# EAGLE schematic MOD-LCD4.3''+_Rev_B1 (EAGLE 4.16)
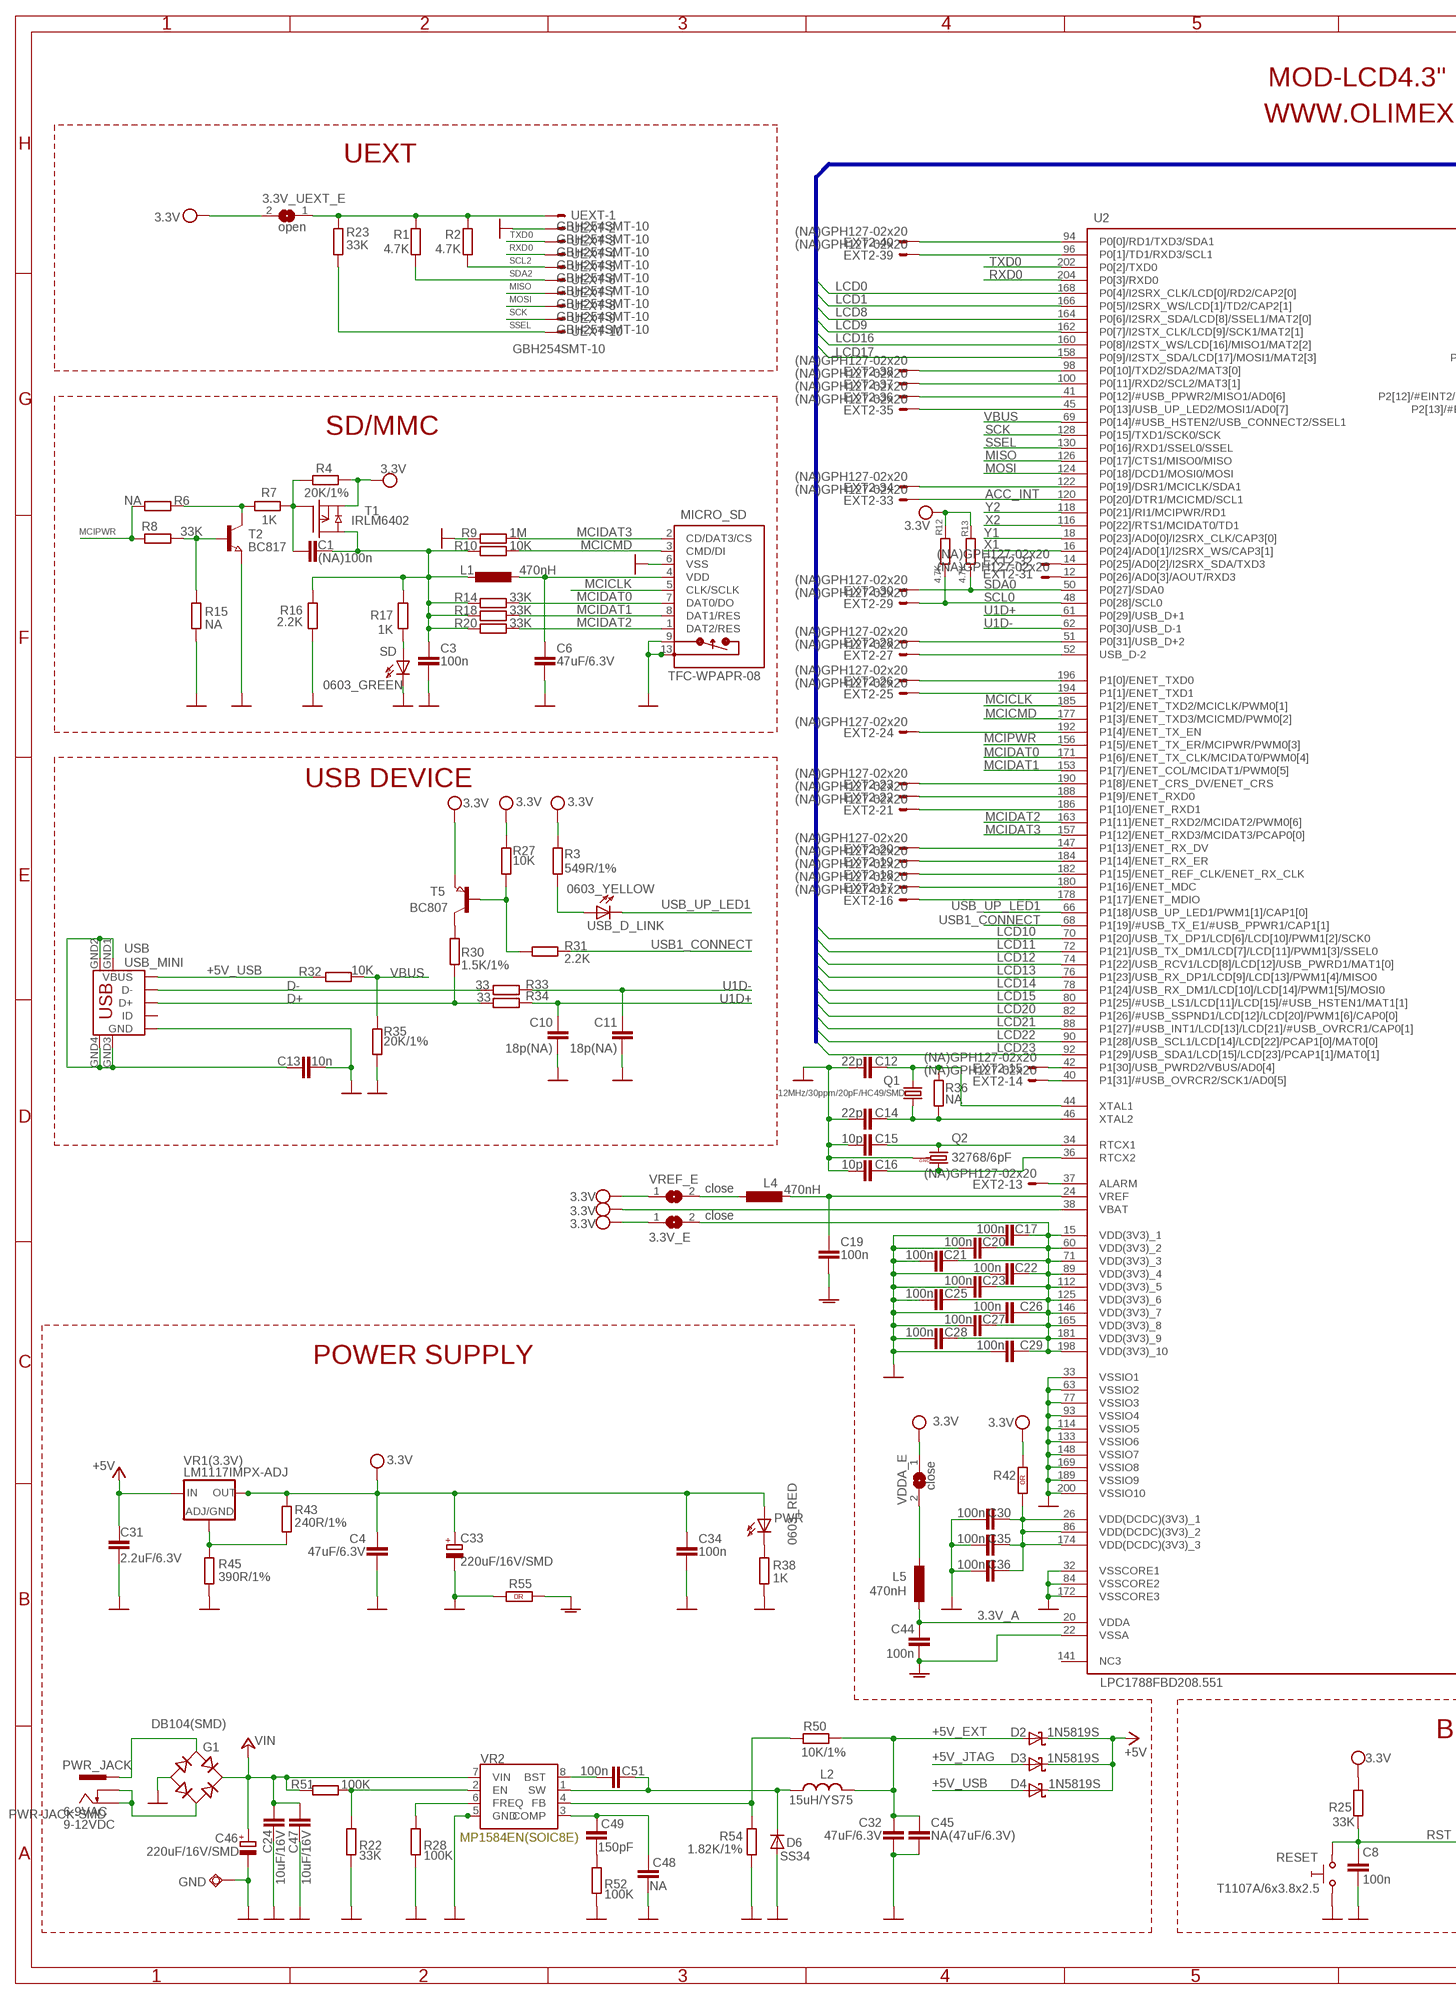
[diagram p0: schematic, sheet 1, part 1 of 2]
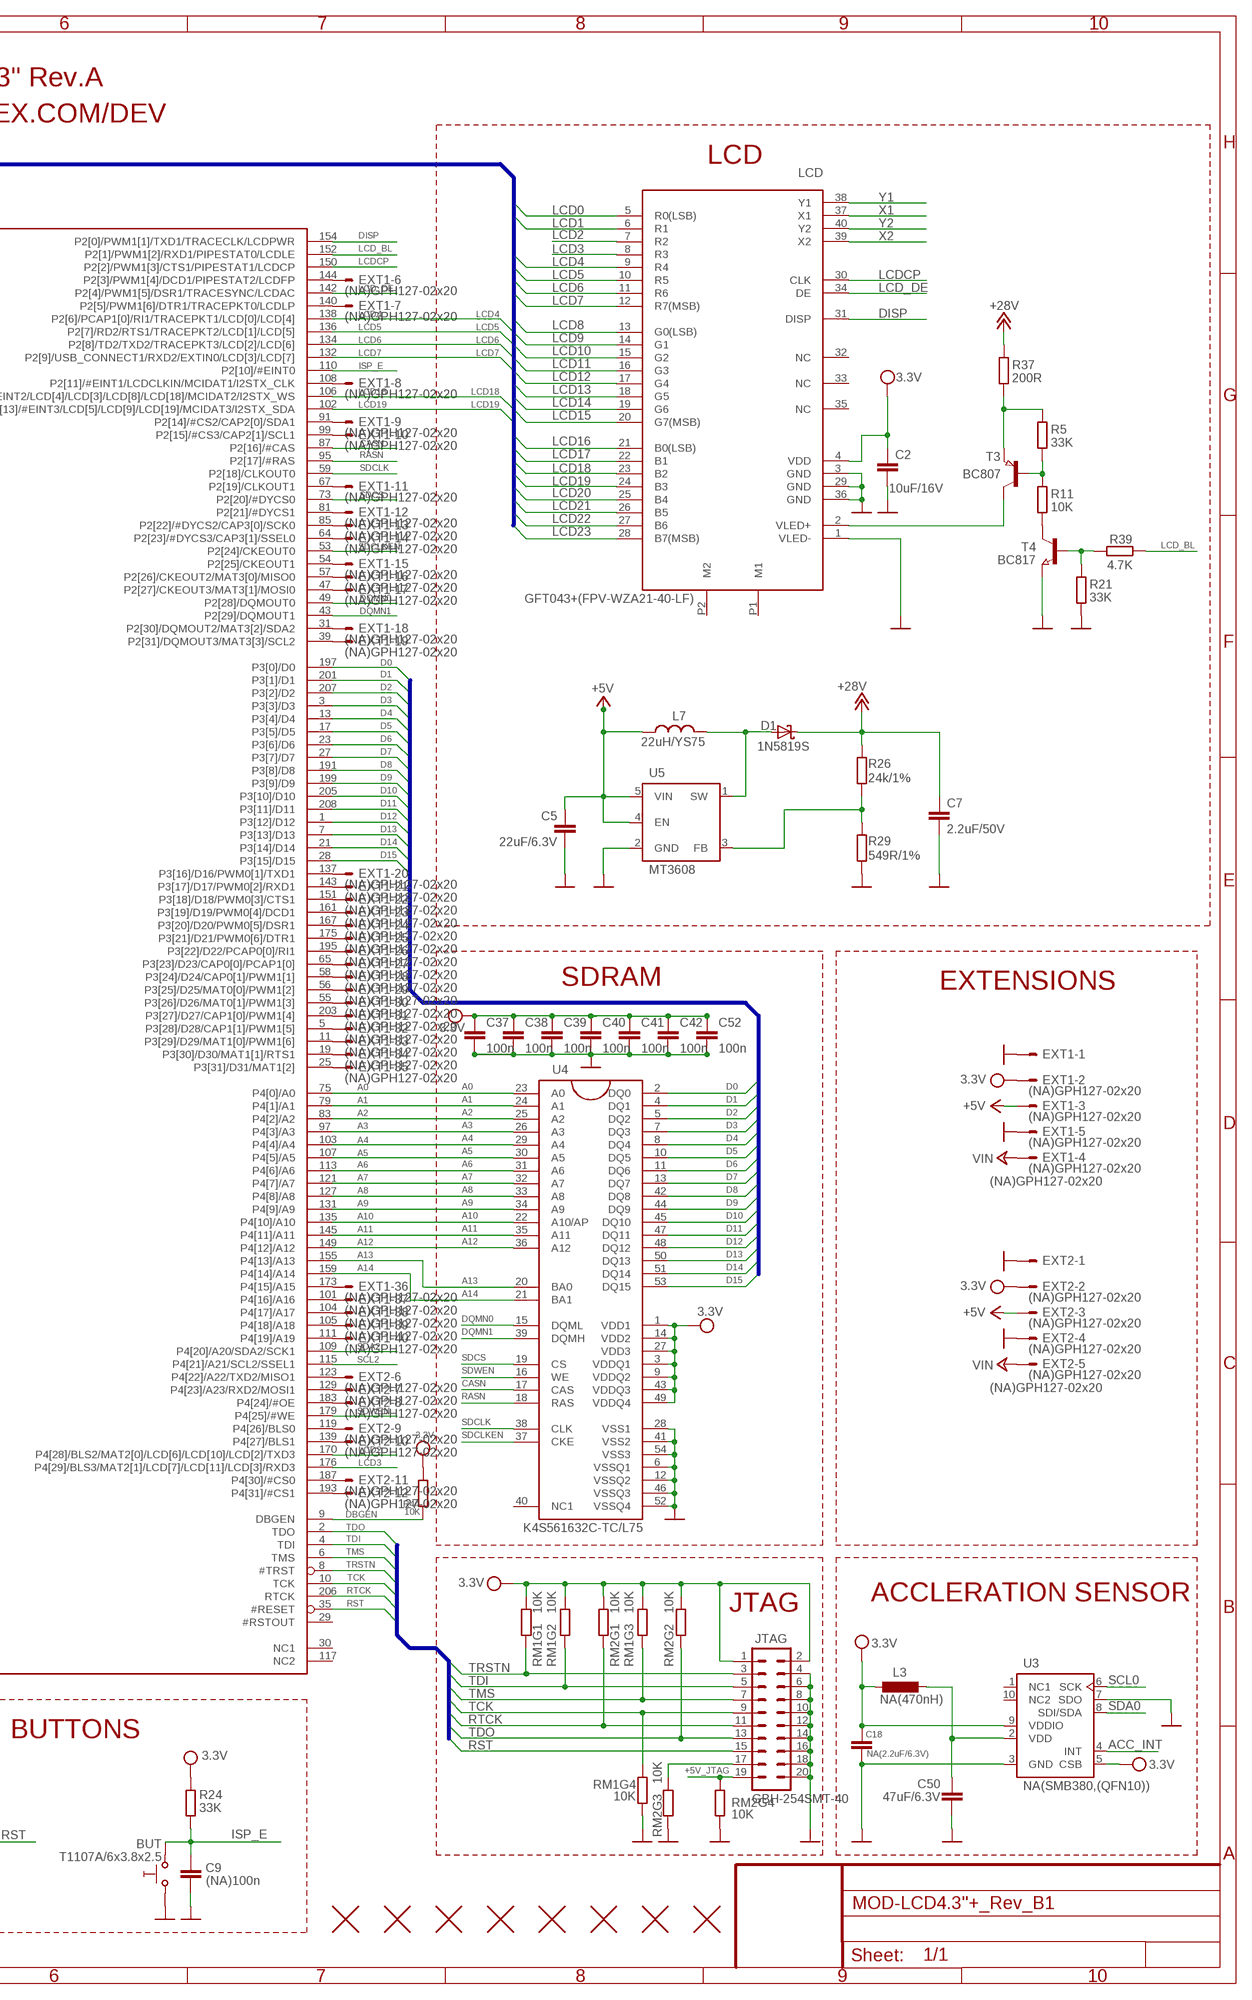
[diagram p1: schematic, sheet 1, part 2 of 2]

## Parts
3.3V_E  close  SJSJ_1_SMALLER_CLOSE  [SJ_1_SMALLER_CLOSE]
3.3V_UEXT_E  open  SJSJ_SMALLER  [SJ_1_SMALLER]
BUT  T1107A/6x3.8x2.5  SW-TAKT6  [SW-TAKT_6X3.5_SMD]
C1  (NA)100n  C0603  [C0603]
C2  10uF/16V  C-EUC0805_5MIL_DWS  [C0805_5MIL_DWS]
C3  100n  C0603  [C0603]
C4  47uF/6.3V  C0805  [C0805]
C5  22uF/6.3V  C-EUC0603_DWS  [C0603_DWS]
C6  47uF/6.3V  C0805  [C0805]
C7  2.2uF/50V  C-EUC0603_DWS  [C0603_DWS]
C8  100n  C0603  [C0603]
C9  (NA)100n  C0603  [C0603]
C10  18p(NA)  C0603  [C0603]
C11  18p(NA)  C0603  [C0603]
C12  22p  C0603  [C0603]
C13  10n  C0603  [C0603]
C14  22p  C0603  [C0603]
C15  10p  C0603  [C0603]
C16  10p  C0603  [C0603]
C17  100n  C0603  [C0603]
C18  NA(2.2uF/6.3V)  C0603  [C0603]
C19  100n  C0603  [C0603]
C20  100n  C0603  [C0603]
C21  100n  C0603  [C0603]
C22  100n  C0603  [C0603]
C23  100n  C0603  [C0603]
C24  10uF/16V  C-EUC0805_5MIL_DWS  [C0805_5MIL_DWS]
C25  100n  C0603  [C0603]
C26  100n  C0603  [C0603]
C27  100n  C0603  [C0603]
C28  100n  C0603  [C0603]
C29  100n  C0603  [C0603]
C30  100n  C0603  [C0603]
C31  2.2uF/6.3V  C-EUC0603_DWS  [C0603_DWS]
C32  47uF/6.3V  C0805  [C0805]
C33  220uF/16V/SMD  CPOL-EU153CLV-0605  [153CLV-0605]
C34  100n  C0603  [C0603]
C35  100n  C0603  [C0603]
C36  100n  C0603  [C0603]
C37  100n  C0603  [C0603]
C38  100n  C0603  [C0603]
C39  100n  C0603  [C0603]
C40  100n  C0603  [C0603]
C41  100n  C0603  [C0603]
C42  100n  C0603  [C0603]
C44  100n  C0603  [C0603]
C45  NA(47uF/6.3V)  C0805  [C0805]
C46  220uF/16V/SMD  CPOL-EU153CLV-0605  [153CLV-0605]
C47  10uF/16V  C-EUC0805_5MIL_DWS  [C0805_5MIL_DWS]
C48  NA  C0603  [C0603]
C49  150pF  C0603  [C0603]
C50  47uF/6.3V  C0805  [C0805]
C51  100n  C0603  [C0603]
C52  100n  C0603  [C0603]
D1  1N5819S  SCHOTKKY7.62SS2  [MLL-41]
D2  1N5819S  SCHOTKKY7.62SS2  [MLL-41]
D3  1N5819S  SCHOTKKY7.62SS2  [MLL-41]
D4  1N5819S  SCHOTKKY7.62SS2  [MLL-41]
D6  SS34  D-MLL-41  [MELF-MLL41]
EXT1  (NA)GPH127-02x20  ML40M50E  [ML40_50MILS_M]
EXT2  (NA)GPH127-02x20  ML40M50E  [ML40_50MILS_M]
G1  DB104(SMD)  B-DIL3  [DB104_SMD]
GND  TESTPAD3  [TEST_PAD40/70/SQUARE]
JTAG  GBH-254SMT-40  ML20MD  [ML20_S]
L1  470nH  L-EUL0805  [L0805]
L2  15uH/YS75  LLQH88PN100M38  [8X8MM_3131]
L3  NA(470nH)  L-EUL0805  [L0805]
L4  470nH  L-EUL0805  [L0805]
L5  470nH  L-EUL0805  [L0805]
L7  22uH/YS75  LLQH88PN100M38  [8X8MM_3131]
LCD  GFT043+(FPV-WZA21-40-LF)  [GFT043(40PINS)]
MICRO_SD  TFC-WPAPR-08  MICRO_SD/MMC_CP_NEWTFC-WPAPR-08  [TFC-WPAPR-08]
PWR  0603_RED  LED0603DWS  [LED-0603]
PWR_JACK  PWR-JACK-SMD  PWR-JAKDCJ-W  [PWR-JACK-SMD]
Q1  12MHz/30ppm/20pF/HC49/SMD  HC49/SHC49/SMD_THIN&SHORT  [HC49/SMD2_THIN&SHORT]
Q2  32768/6pF  Q_GND1  [TC26H_3_REPAIR_SMD]
R1  4.7K  R-EU_R0603  [R0603]
R2  4.7K  R-EU_R0603  [R0603]
R3  549R/1%  R-EU_R0603  [R0603]
R4  20K/1%  R0603  [R0603]
R5  33K  R0603  [R0603]
R6  NA  R0603  [R0603]
R7  1K  R0603  [R0603]
R8  33K  R0603  [R0603]
R9  1M  R0603  [R0603]
R10  10K  R0603  [R0603]
R11  10K  R0603  [R0603]
R12  4.7K  R-EU_R0603  [R0603]
R13  4.7K  R-EU_R0603  [R0603]
R14  33K  R0603  [R0603]
R15  NA  R0603  [R0603]
R16  2.2K  R0603  [R0603]
R17  1K  R0603  [R0603]
R18  33K  R0603  [R0603]
R20  33K  R0603  [R0603]
R21  33K  R0603  [R0603]
R22  33K  R-EU_R0603  [R0603]
R23  33K  R0603  [R0603]
R24  33K  R0603  [R0603]
R25  33K  R0603  [R0603]
R26  24k/1%  R-EU_R0603  [R0603]
R27  10K  R0603  [R0603]
R28  100K  R-EU_R0603  [R0603]
R29  549R/1%  R-EU_R0603  [R0603]
R30  1.5K/1%  R0603  [R0603]
R31  2.2K  R0603  [R0603]
R32  10K  R0603  [R0603]
R33  33  R0603  [R0603]
R34  33  R0603  [R0603]
R35  20K/1%  R0603  [R0603]
R36  NA  R-EU_R0603  [R0603]
R37  200R  R0805  [R0805]
R38  1K  R0603  [R0603]
R39  4.7K  R-EU_R0603  [R0603]
R42  R_0R0R(NA)  [0603_0R]
R43  240R/1%  R-EU_R0603  [R0603]
R44  10K  R0603  [R0603]
R45  390R/1%  R-EU_R0603  [R0603]
R50  10K/1%  R-EU_R0603  [R0603]
R51  100K  R-EU_R0603  [R0603]
R52  100K  R-EU_R0603  [R0603]
R54  1.82K/1%  R-EU_R0603  [R0603]
R55  R_0R0R(NA)  [0603_0R]
RESET  T1107A/6x3.8x2.5  SW-TAKT6  [SW-TAKT_6X3.5_SMD]
RM1  10K  R_MATRIX_4E  [R_MATRIX_4]
RM2  10K  R_MATRIX_4E  [R_MATRIX_4]
SD  0603_GREEN  LED0603DWS  [LED-0603]
T1  IRLM6402  IRLML6402  [SOT23]
T2  BC817  NPN-TRANSISTOR_SOT23  [SOT23]
T3  BC807  PNP-TRANSISTOR_SOT23  [SOT23]
T4  BC817  NPN-TRANSISTOR_SOT23  [SOT23]
T5  BC807  PNP-TRANSISTOR_SOT23  [SOT23]
U2  LPC1788FBD208.551  LPC2478""  [LQFP208]
U3  NA(SMB380,(QFN10))  SMB3801  [QFN10]
U4  K4S561632C-TC/L75  [54TSOPII]
U5  MT3608  [SOT23-6]
U$1  FIDUCIAL1X2  [FIDUCIAL-1X2]
U$2  FIDUCIAL1X2  [FIDUCIAL-1X2]
U$3  FIDUCIAL1X2  [FIDUCIAL-1X2]
U$6  FIDUCIAL1X2  [FIDUCIAL-1X2]
U$9  FIDUCIAL1X2  [FIDUCIAL-1X2]
U$10  FIDUCIAL1X2  [FIDUCIAL-1X2]
U$12  FIDUCIAL1X2  [FIDUCIAL-1X2]
U$13  FIDUCIAL1X2  [FIDUCIAL-1X2]
UEXT  GBH254SMT-10  ML10MDE  [ML10_S]
USB  USB_MINI  MINI_USB9  [USB_MINI_9PIN]
USB_D_LINK  0603_YELLOW  LED0603DWS  [LED-0603]
VDDA_E  close  SJSJ_1_SMALLER_CLOSE  [SJ_1_SMALLER_CLOSE]
VR1(3.3V)  LM1117IMPX-ADJ  LM1117  [SOT223]
VR2  MP1584EN(SOIC8E)  [SOIC8E]
VREF_E  close  SJSJ_1_SMALLER_CLOSE  [SJ_1_SMALLER_CLOSE]

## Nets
3.3V_A: C44.2 L5.1 U2.20(VDDA)
3.3V_MCU: 3.3V_E.2 C17.2 C20.2 C21.2 C22.2 C23.2 C25.2 C26.2 C27.2 C28.2 C29.2 U2.15(VDD(3V3)_1) U2.60(VDD(3V3)_2) U2.71(VDD(3V3)_3) U2.89(VDD(3V3)_4) U2.112(VDD(3V3)_5) U2.125(VDD(3V3)_6) U2.146(VDD(3V3)_7) U2.165(VDD(3V3)_8) U2.181(VDD(3V3)_9) U2.198(VDD(3V3)_10)
+5V: C5.1 C31.1 D2.K(C) D3.K(C) D4.K(C) EXT1.3 EXT2.3 L7.1 U5.4(EN) U5.5(VIN) VR1(3.3V).3(IN)
+5V_EXT: C32.2 C45.2 D2.A L2.2 R50.2
+5V_JTAG: D3.A JTAG.19 RM2.4.2
+5V_USB: D4.A R32.1 USB.VBUS
+12V: C7.1 D1.K(C) R26.2 R37.1 ; supply symbol labelled +28V
+24V: C24.1 C46.+ C47.1 EXT1.4 EXT2.5 G1.+ R51.2 VR2.7(VIN) ; supply symbol labelled VIN
A0: U2.75(P4[0]/A0) U4.23(A0)
A1: U2.79(P4[1]/A1) U4.24(A1)
A2: U2.83(P4[2]/A2) U4.25(A2)
A3: U2.97(P4[3]/A3) U4.26(A3)
A4: U2.103(P4[4]/A4) U4.29(A4)
A5: U2.107(P4[5]/A5) U4.30(A5)
A6: U2.113(P4[6]/A6) U4.31(A6)
A7: U2.121(P4[7]/A7) U4.32(A7)
A8: U2.127(P4[8]/A8) U4.33(A8)
A9: U2.131(P4[9]/A9) U4.34(A9)
A10: U2.135(P4[10]/A10) U4.22(A10/AP)
A11: U2.145(P4[11]/A11) U4.35(A11)
A12: U2.149(P4[12]/A12) U4.36(A12)
A13: U2.155(P4[13]/A13) U4.20(BA0)
A14: U2.159(P4[14]/A14) U4.21(BA1)
ACC_INT: EXT2.33 U2.120(P0[20]/DTR1/MCICMD/SCL1) U3.4(INT)
CASN: U2.87(P2[16]/#CAS) U4.17(CAS)
D0: U2.197(P3[0]/D0) U4.2(DQ0)
D1: U2.201(P3[1]/D1) U4.4(DQ1)
D2: U2.207(P3[2]/D2) U4.5(DQ2)
D3: U2.3(P3[3]/D3) U4.7(DQ3)
D4: U2.13(P3[4]/D4) U4.8(DQ4)
D5: U2.17(P3[5]/D5) U4.10(DQ5)
D6: U2.23(P3[6]/D6) U4.11(DQ6)
D7: U2.27(P3[7]/D7) U4.13(DQ7)
D8: U2.191(P3[8]/D8) U4.42(DQ8)
D9: U2.199(P3[9]/D9) U4.44(DQ9)
D10: U2.205(P3[10]/D10) U4.45(DQ10)
D11: U2.208(P3[11]/D11) U4.47(DQ11)
D12: U2.1(P3[12]/D12) U4.48(DQ12)
D13: U2.7(P3[13]/D13) U4.50(DQ13)
D14: U2.21(P3[14]/D14) U4.51(DQ14)
D15: U2.28(P3[15]/D15) U4.53(DQ15)
D+: R30.1 R34.1 USB.D+
D-: R33.1 USB.D-
DBGEN: R44.1 U2.9(DBGEN)
DISP: LCD.31(DISP) U2.154(P2[0]/PWM1[1]/TXD1/TRACECLK/LCDPWR)
DQMN0: U2.49(P2[28]/DQMOUT0) U4.15(DQML)
DQMN1: U2.43(P2[29]/DQMOUT1) U4.39(DQMH)
GND: BUT.P$2 C2.2 C3.1 C4.1 C5.2 C6.1 C7.2 C8.1 C9.1 C10.2 C11.2 C12.1 C13.1 C14.1 C15.1 C16.1 C17.1 C18.1 C20.1 C21.1 C22.1 C23.1 C24.2 C25.1 C26.1 C27.1 C28.1 C29.1 C30.1 C31.2 C32.1 C33.- C34.1 C35.1 C36.1 C37.1 C38.1 C39.1 C40.1 C41.1 C42.1 C45.1 C46.- C47.2 C48.2 C50.1 C52.1 D6.2(A) EXT1.1 EXT1.5 EXT2.1 EXT2.4 G1.- GND.P$1(PP) JTAG.4 JTAG.6 JTAG.8 JTAG.10 JTAG.12 JTAG.14 JTAG.16 JTAG.18 JTAG.20 LCD.1(VLED-) LCD.3(GND) LCD.29(GND) LCD.36(GND) MICRO_SD.6(VSS) MICRO_SD.9(CP_E) MICRO_SD.10(PACK1) MICRO_SD.11(PACK2) MICRO_SD.12(PACK3) MICRO_SD.13(PACK4) Q2.GND R9.1 R15.1 R16.1 R21.2 R22.1 R28.1 R29.1 R35.2 R38.2 R45.1 R52.1 R54.1 R55.2(1.2) RESET.P$2 RM1.4.1 RM2.3.1 RM2.4.1 SD.C T2.2(E) T4.2(E) U2.32(VSSCORE1) U2.33(VSSIO1) U2.63(VSSIO2) U2.77(VSSIO3) U2.84(VSSCORE2) U2.93(VSSIO4) U2.114(VSSIO5) U2.133(VSSIO6) U2.148(VSSIO7) U2.169(VSSIO8) U2.172(VSSCORE3) U2.189(VSSIO9) U2.200(VSSIO10) U3.3(GND) U3.7(SDO) U4.6(VSSQ1) U4.12(VSSQ2) U4.28(VSS1) U4.41(VSS2) U4.46(VSSQ3) U4.52(VSSQ4) U4.54(VSS3) U5.2(GND) UEXT.2 USB.GND VR2.5(GND) VR2.EP VR2.EP1(EP)
GNDA: C19.1 C44.1 R55.1(1.1) U2.22(VSSA)
ISP_E: BUT.P$1 C9.2 R24.1 U2.110(P2[10]/#EINT0)
LCD0: LCD.5(R0(LSB)) U2.168(P0[4]/I2SRX_CLK/LCD[0]/RD2/CAP2[0])
LCD1: LCD.6(R1) U2.166(P0[5]/I2SRX_WS/LCD[1]/TD2/CAP2[1])
LCD2: LCD.7(R2) U2.170(P4[28]/BLS2/MAT2[0]/LCD[6]/LCD[10]/LCD[2]/TXD3)
LCD3: LCD.8(R3) U2.176(P4[29]/BLS3/MAT2[1]/LCD[7]/LCD[11]/LCD[3]/RXD3)
LCD4: LCD.9(R4) U2.138(P2[6]/PCAP1[0]/RI1/TRACEPKT1/LCD[0]/LCD[4])
LCD5: LCD.10(R5) U2.136(P2[7]/RD2/RTS1/TRACEPKT2/LCD[1]/LCD[5])
LCD6: LCD.11(R6) U2.134(P2[8]/TD2/TXD2/TRACEPKT3/LCD[2]/LCD[6])
LCD7: LCD.12(R7(MSB)) U2.132(P2[9]/USB_CONNECT1/RXD2/EXTIN0/LCD[3]/LCD[7])
LCD8: LCD.13(G0(LSB)) U2.164(P0[6]/I2SRX_SDA/LCD[8]/SSEL1/MAT2[0])
LCD9: LCD.14(G1) U2.162(P0[7]/I2STX_CLK/LCD[9]/SCK1/MAT2[1])
LCD10: LCD.15(G2) U2.70(P1[20]/USB_TX_DP1/LCD[6]/LCD[10]/PWM1[2]/SCK0)
LCD11: LCD.16(G3) U2.72(P1[21]/USB_TX_DM1/LCD[7]/LCD[11]/PWM1[3]/SSEL0)
LCD12: LCD.17(G4) U2.74(P1[22]/USB_RCV1/LCD[8]/LCD[12]/USB_PWRD1/MAT1[0])
LCD13: LCD.18(G5) U2.76(P1[23]/USB_RX_DP1/LCD[9]/LCD[13]/PWM1[4]/MISO0)
LCD14: LCD.19(G6) U2.78(P1[24]/USB_RX_DM1/LCD[10]/LCD[14]/PWM1[5]/MOSI0)
LCD15: LCD.20(G7(MSB)) U2.80(P1[25]/#USB_LS1/LCD[11]/LCD[15]/#USB_HSTEN1/MAT1[1])
LCD16: LCD.21(B0(LSB)) U2.160(P0[8]/I2STX_WS/LCD[16]/MISO1/MAT2[2])
LCD17: LCD.22(B1) U2.158(P0[9]/I2STX_SDA/LCD[17]/MOSI1/MAT2[3])
LCD18: LCD.23(B2) U2.106(P2[12]/#EINT2/LCD[4]/LCD[3]/LCD[8]/LCD[18]/MCIDAT2/I2STX_WS)
LCD19: LCD.24(B3) U2.102(P2[13]/#EINT3/LCD[5]/LCD[9]/LCD[19]/MCIDAT3/I2STX_SDA)
LCD20: LCD.25(B4) U2.82(P1[26]/#USB_SSPND1/LCD[12]/LCD[20]/PWM1[6]/CAP0[0])
LCD21: LCD.26(B5) U2.88(P1[27]/#USB_INT1/LCD[13]/LCD[21]/#USB_OVRCR1/CAP0[1])
LCD22: LCD.27(B6) U2.90(P1[28]/USB_SCL1/LCD[14]/LCD[22]/PCAP1[0]/MAT0[0])
LCD23: LCD.28(B7(MSB)) U2.92(P1[29]/USB_SDA1/LCD[15]/LCD[23]/PCAP1[1]/MAT0[1])
LCD_BL: R39.1 U2.152(P2[1]/PWM1[2]/RXD1/PIPESTAT0/LCDLE)
LCD_DE: LCD.34(DE) U2.142(P2[4]/PWM1[5]/DSR1/TRACESYNC/LCDAC)
LCDCP: LCD.30(CLK) U2.150(P2[2]/PWM1[3]/CTS1/PIPESTAT1/LCDCP)
MCICLK: MICRO_SD.5(CLK/SCLK) U2.185(P1[2]/ENET_TXD2/MCICLK/PWM0[1])
MCICMD: MICRO_SD.3(CMD/DI) R10.2 U2.177(P1[3]/ENET_TXD3/MCICMD/PWM0[2])
MCIDAT0: MICRO_SD.7(DAT0/DO) R14.2 U2.171(P1[6]/ENET_TX_CLK/MCIDAT0/PWM0[4])
MCIDAT1: MICRO_SD.8(DAT1/RES) R18.2 U2.153(P1[7]/ENET_COL/MCIDAT1/PWM0[5])
MCIDAT2: MICRO_SD.1(DAT2/RES) R20.2 U2.163(P1[11]/ENET_RXD2/MCIDAT2/PWM0[6])
MCIDAT3: MICRO_SD.2(CD/DAT3/CS) R9.2 U2.157(P1[12]/ENET_RXD3/MCIDAT3/PCAP0[0])
MCIPWR: R6.2 R8.2 U2.156(P1[5]/ENET_TX_ER/MCIPWR/PWM0[3])
MISO: U2.126(P0[17]/CTS1/MISO0/MISO) UEXT.7
MMC_VDD: C6.2 L1.1 MICRO_SD.4(VDD)
MOSI: U2.124(P0[18]/DCD1/MOSI0/MOSI) UEXT.8
N$1: C50.2 L3.1 U3.2(VDD)
N$2: C12.2 Q1.1 R36.2 U2.44(XTAL1)
N$3: L5.2 VDDA_E.2
N$4: LCD.2(VLED+) T3.3(C)
N$5: R5.2 R11.2 T3.1(B)
N$6: R11.1 T4.3(C)
N$7: C14.2 Q1.2 R36.1 U2.46(XTAL2)
N$8: C15.2 Q2.2 U2.34(RTCX1)
N$9: C16.2 Q2.1 U2.36(RTCX2)
N$10: R21.1 R39.2 T4.1(B)
N$11: 3.3V_UEXT_E.1 R1.2 R2.2 R23.2 UEXT.1
N$12: EXT1.6 U2.144(P2[3]/PWM1[4]/DCD1/PIPESTAT2/LCDFP)
N$13: EXT1.7 U2.140(P2[5]/PWM1[6]/DTR1/TRACEPKT0/LCDLP)
N$14: EXT1.8 U2.108(P2[11]/#EINT1/LCDCLKIN/MCIDAT1/I2STX_CLK)
N$15: EXT1.9 U2.91(P2[14]/#CS2/CAP2[0]/SDA1)
N$16: R8.1 R15.2 T2.1(B)
N$17: EXT1.10 U2.99(P2[15]/#CS3/CAP2[1]/SCL1)
N$18: EXT1.11 U2.67(P2[19]/CLKOUT1)
N$19: EXT1.12 U2.81(P2[21]/#DYCS1)
N$20: EXT1.13 U2.85(P2[22]/#DYCS2/CAP3[0]/SCK0)
N$21: EXT1.14 U2.64(P2[23]/#DYCS3/CAP3[1]/SSEL0)
N$22: EXT1.15 U2.54(P2[25]/CKEOUT1)
N$23: EXT1.16 U2.57(P2[26]/CKEOUT2/MAT3[0]/MISO0)
N$24: EXT1.17 U2.47(P2[27]/CKEOUT3/MAT3[1]/MOSI0)
N$25: EXT1.18 U2.31(P2[30]/DQMOUT2/MAT3[2]/SDA2)
N$26: EXT1.19 U2.39(P2[31]/DQMOUT3/MAT3[3]/SCL2)
N$27: EXT1.20 U2.137(P3[16]/D16/PWM0[1]/TXD1)
N$28: EXT1.21 U2.143(P3[17]/D17/PWM0[2]/RXD1)
N$29 [pwr]: C51.1 D6.1(C) L2.1 VR2.1(SW)
N$30: EXT1.22 U2.151(P3[18]/D18/PWM0[3]/CTS1)
N$31: R26.1 R29.2 U5.3(FB)
N$32: EXT1.23 U2.161(P3[19]/D19/PWM0[4]/DCD1)
N$33: EXT1.24 U2.167(P3[20]/D20/PWM0[5]/DSR1)
N$34: EXT1.25 U2.175(P3[21]/D21/PWM0[6]/DTR1)
N$35 [pwr]: R50.1 R54.2 VR2.4(FB)
N$36: EXT1.26 U2.195(P3[22]/D22/PCAP0[0]/RI1)
N$37: EXT1.27 U2.65(P3[23]/D23/CAP0[0]/PCAP1[0])
N$38: EXT1.28 U2.58(P3[24]/D24/CAP0[1]/PWM1[1])
N$39: EXT1.29 U2.56(P3[25]/D25/MAT0[0]/PWM1[2])
N$40: EXT1.30 U2.55(P3[26]/D26/MAT0[1]/PWM1[3])
N$41: EXT1.31 U2.203(P3[27]/D27/CAP1[0]/PWM1[4])
N$42: JTAG.17 RM2.3.2
N$43: R6.1 R7.2 T2.3(C)
N$44: EXT1.32 U2.5(P3[28]/D28/CAP1[1]/PWM1[5])
N$45: EXT1.33 U2.11(P3[29]/D29/MAT1[0]/PWM1[6])
N$46: EXT1.34 U2.19(P3[30]/D30/MAT1[1]/RTS1)
N$47: EXT1.35 U2.25(P3[31]/D31/MAT1[2])
N$48: EXT1.36 U2.173(P4[15]/A15)
N$49: EXT1.37 U2.101(P4[16]/A16)
N$50: EXT1.38 U2.104(P4[17]/A17)
N$51: EXT1.39 U2.105(P4[18]/A18)
N$52: R30.2 T5.3(C)
N$53: EXT1.40 U2.111(P4[19]/A19)
N$54: R27.2 R31.2 T5.1(B)
N$55: EXT2.6 U2.123(P4[22]/A22/TXD2/MISO1)
N$56: EXT2.7 U2.129(P4[23]/A23/RXD2/MOSI1)
N$57: EXT2.8 U2.183(P4[24]/#OE)
N$58: R17.2 SD.A
N$59: C13.2 USB.GND1 USB.GND2 USB.GND3 USB.GND4
N$60: R3.1 USB_D_LINK.A
N$61: C1.2 C3.2 L1.2 R10.1 R14.1 R16.2 R17.1 R18.1 R20.1 T1.3(D)
N$62: C1.1 R4.2 R7.1 T1.1(G)
N$63: EXT2.9 U2.119(P4[26]/BLS0)
N$64: C49.2 R52.2
N$65 [pwr]: C51.2 VR2.8(BST)
N$66: EXT2.10 U2.139(P4[27]/BLS1)
N$67: R43.1 R45.2 VR1(3.3V).1(ADJ/GND)
N$69 [pwr]: C48.1 C49.1 VR2.3(COMP)
N$70 [pwr]: R22.2 R51.1 VR2.2(EN)
N$71: EXT2.11 U2.187(P4[30]/#CS0)
N$72: EXT2.12 U2.193(P4[31]/#CS1)
N$73: EXT2.13 U2.37(ALARM)
N$74: R28.2 VR2.6(FREQ)
N$75: EXT2.14 U2.40(P1[31]/#USB_OVRCR2/SCK1/AD0[5])
N$76: EXT2.15 U2.42(P1[30]/USB_PWRD2/VBUS/AD0[4])
N$77: EXT2.16 U2.178(P1[17]/ENET_MDIO)
N$79: EXT2.17 U2.180(P1[16]/ENET_MDC)
N$80: EXT2.18 U2.182(P1[15]/ENET_REF_CLK/ENET_RX_CLK)
N$82: EXT2.19 U2.184(P1[14]/ENET_RX_ER)
N$83: EXT2.20 U2.147(P1[13]/ENET_RX_DV)
N$84: EXT2.21 U2.186(P1[10]/ENET_RXD1)
N$85: EXT2.22 U2.188(P1[9]/ENET_RXD0)
N$86: EXT2.23 U2.190(P1[8]/ENET_CRS_DV/ENET_CRS)
N$87: C19.2 L4.2 U2.24(VREF)
N$88: EXT2.24 U2.192(P1[4]/ENET_TX_EN)
N$89: EXT2.25 U2.194(P1[1]/ENET_TXD1)
N$90: EXT2.26 U2.196(P1[0]/ENET_TXD0)
N$91: EXT2.27 U2.52(USB_D-2)
N$92: EXT2.28 U2.51(P0[31]/USB_D+2)
N$93: EXT2.31 U2.12(P0[26]/AD0[3]/AOUT/RXD3)
N$94: EXT2.32 U2.14(P0[25]/AD0[2]/I2SRX_SDA/TXD3)
N$95: EXT2.34 U2.122(P0[19]/DSR1/MCICLK/SDA1)
N$96: EXT2.35 U2.45(P0[13]/USB_UP_LED2/MOSI1/AD0[7])
N$97: EXT2.36 U2.41(P0[12]/#USB_PPWR2/MISO1/AD0[6])
N$98: EXT2.37 U2.100(P0[11]/RXD2/SCL2/MAT3[1])
N$99: EXT2.38 U2.98(P0[10]/TXD2/SDA2/MAT3[0])
N$100: PWR.C R38.1
N$101: EXT2.39 U2.96(P0[1]/TD1/RXD3/SCL1)
N$102: EXT2.40 U2.94(P0[0]/RD1/TXD3/SDA1)
N$103: D1.A L7.2 U5.1(SW)
N$104: G1.AC2 PWR_JACK.2(-) PWR_JACK.3(--)
N$105: G1.AC1 PWR_JACK.1(+)
N$106: R5.1 R37.2 T3.2(E)
N$112: L4.1 VREF_E.2
RASN: U2.95(P2[17]/#RAS) U4.18(RAS)
RST: C8.2 JTAG.15 R25.1 RESET.P$1 U2.35(#RESET)
RTCK: JTAG.11 RM2.1.2 U2.206(RTCK)
RXD0: U2.204(P0[3]/RXD0) UEXT.4
SCK: U2.128(P0[15]/TXD1/SCK0/SCK) UEXT.9
SCL0: EXT2.29 R12.2 U2.48(P0[28]/SCL0) U3.6(SCK)
SCL2: R2.1 U2.115(P4[21]/A21/SCL2/SSEL1) UEXT.5
SDA0: EXT2.30 R13.2 U2.50(P0[27]/SDA0) U3.8(SDI/SDA)
SDA2: R1.1 U2.109(P4[20]/A20/SDA2/SCK1) UEXT.6
SDCLK: U2.59(P2[18]/CLKOUT0) U4.38(CLK)
SDCLKEN: U2.53(P2[24]/CKEOUT0) U4.37(CKE)
SDCS: U2.73(P2[20]/#DYCS0) U4.19(CS)
SDWEN: U2.179(P4[25]/#WE) U4.16(WE)
SSEL: R23.1 U2.130(P0[16]/RXD1/SSEL0/SSEL) UEXT.10
TCK: JTAG.9 RM1.4.2 U2.10(TCK)
TDI: JTAG.5 RM1.2.2 U2.4(TDI)
TDO: JTAG.13 RM2.2.2 U2.2(TDO)
TMS: JTAG.7 RM1.3.2 U2.6(TMS)
TRSTN: JTAG.3 RM1.1.2 U2.8(#TRST)
TXD0: U2.202(P0[2]/TXD0) UEXT.3
U1D+: C10.1 R34.2 U2.61(P0[29]/USB_D+1)
U1D-: C11.1 R33.2 U2.62(P0[30]/USB_D-1)
USB1_CONNECT: R31.1 U2.68(P1[19]/#USB_TX_E1/#USB_PPWR1/CAP1[1])
USB_UP_LED1: U2.66(P1[18]/USB_UP_LED1/PWM1[1]/CAP1[0]) USB_D_LINK.C
VBUS: R32.2 R35.1 U2.69(P0[14]/#USB_HSTEN2/USB_CONNECT2/SSEL1)
VCC: 3.3V_E.1 3.3V_UEXT_E.2 C2.1 C4.2 C18.2 C33.+ C34.2 C37.2 C38.2 C39.2 C40.2 C41.2 C42.2 C52.2 EXT1.2 EXT2.2 JTAG.1 JTAG.2 L3.2 LCD.4(VDD) PWR.A R3.2 R4.1 R12.1 R13.1 R24.2 R25.2 R27.1 R42.2(1.2) R43.2 R44.2 RM1.1.1 RM1.2.1 RM1.3.1 RM2.1.1 RM2.2.1 T1.2(S) T5.2(E) U2.38(VBAT) U3.5(CSB) U3.9(VDDIO) U4.1(VDD1) U4.3(VDDQ1) U4.9(VDDQ2) U4.14(VDD2) U4.27(VDD3) U4.43(VDDQ3) U4.49(VDDQ4) VDDA_E.1 VR1(3.3V).2(OUT) VR1(3.3V).4(RAD) VREF_E.1 ; supply symbol labelled 3.3V
VDC_DC: C30.2 C35.2 C36.2 R42.1(1.1) U2.26(VDD(DCDC)(3V3)_1) U2.86(VDD(DCDC)(3V3)_2) U2.174(VDD(DCDC)(3V3)_3)
X1: LCD.37(X1) U2.16(P0[24]/AD0[1]/I2SRX_WS/CAP3[1])
X2: LCD.39(X2) U2.116(P0[22]/RTS1/MCIDAT0/TD1)
Y1: LCD.38(Y1) U2.18(P0[23]/AD0[0]/I2SRX_CLK/CAP3[0])
Y2: LCD.40(Y2) U2.118(P0[21]/RI1/MCIPWR/RD1)
Unconnected: LCD.32(NC) LCD.33(NC) LCD.35(NC) LCD.P1(M1) LCD.P2(M2) U2.29(#RSTOUT) U2.30(NC1) U2.117(NC2) U2.141(NC3) U3.1(NC1) U3.10(NC2) U4.40(NC1) USB.ID

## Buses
RST,RTCK,TCK,TRSTN,TMS,TDI,TDO
D[0..15]
LCD[0..1],LCD[4..23]

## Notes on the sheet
- MOD-LCD4.3'' Rev.A
- WWW.OLIMEX.COM/DEV
- UEXT | LCD
- SD/MMC
- USB DEVICE
- SDRAM | EXTENSIONS
- POWER SUPPLY
- ACCLERATION SENSOR
- JTAG
- BUTTONS
- 6-9VAC
- 9-12VDC

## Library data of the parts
3.3V_E 3.3V_UEXT_E VDDA_E VREF_E = jumper:SJ: SMD solder JUMPER
BUT RESET = gogo:SW-TAKT
C1 C3 C4 C6 C8-C23 C25-C30 C32 C34-C42 C44 C45 C48-C52 = DOUBLE-SIDE:C: Capacitor
C2 C5 C7 C24 C31 C47 = rcl:C-EU: CAPACITOR, European symbol
C33 C46 = rcl:CPOL-EU: POLARIZED CAPACITOR, European symbol
D1-D4 = gogo:SCHOTKKY7.62SS
D6 = semicon-smd-ipc:D-: DIODE
EXT1 EXT2 = OLIMEX_CONNECTORS:ML40?E: HARTING
G1 = DOUBLE-SIDE:B-DIL: RECTIFIER
GND = gogo:TESTPAD: drill 40mils, diameter 70mils
JTAG = con-harting-ml:ML20: HARTING
L1 L3-L5 = rcl:L-EU: INDUCTOR, European symbol
L2 L7 = OLIMEX_DISCRET:L
LCD = olimex_lcd:GFT043: Construction: 4.3 inches a-Si color TFT-LCD, White LED / CCFL Backlight and PCB. Resolution (pixel): 480(R.G.B) X272 Number of the Colors : 262K colors ( R , G , B 6 bit digital each) LCD type : Transmissive Color TFT LCD ( normally White) Interface: 40 pin pitch 0.5 FFC Power Supply Voltage: 3.3V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
MICRO_SD = OLIMEX_CONNECTORS:MICRO_SD/MMC_CP_NEW
PWR SD USB_D_LINK = DOUBLE-SIDE:LED
PWR_JACK = gogo:PWR-JAK
Q1 = crystal:HC49/S: CRYSTAL
Q2 = crystal:Q_GND
R1-R3 R12 R13 R22 R26 R28 R29 R36 R39 R43 R45 R50-R52 R54 = rcl:R-EU_: RESISTOR, European symbol
R4-R11 R14-R18 R20 R21 R23-R25 R27 R30-R35 R37 R38 R44 = DOUBLE-SIDE:R: Resistors
R42 R55 = OLIMEX_DISCRET:R_0R
RM1 RM2 = OLIMEX_DISCRET:R_MATRIX_4E
T1 = gogo:IRLML6402
T2 T4 = semicon-smd-ipc:NPN-TRANSISTOR_: NPN TRANSISTOR
T3 T5 = semicon-smd-ipc:PNP-TRANSISTOR_: PNP TRANSISTOR
U2 = OLIMEX_IC:LPC2478
U3 = OLIMEX_IC:SMB380: SMB380 Triaxial acceleration sensor Key Features: -> Three-axis accelerometer; -> Temperature output; -> Small Package - Mold package (QFN-10); -> Digital interface: SPI(4-wire, 3-wire), I2C, interrupt pin; -> Programmable functionality: g-range +-2g/+-4g/+-8g; -> Low current consumption; -> RoHS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
U4 = SIRRUS:K4S561632C-TC/L75
U5 = OLIMEX_IC:MT3608
U$1-U$3 U$6 U$9 U$10 U$12 U$13 = SparkFunEagle-6-6-07:FIDUCIAL: Fiducial Alignment Points
UEXT = con-harting-ml:ML10?E: HARTING
USB = OLIMEX_CONNECTORS:MINI_USB9
VR1(3.3V) = arm:LM1117
VR2 = OLIMEX_IC:MP1584

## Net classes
1 pwr: width 0.25 mm
2 gnd: width 0.25 mm, clearance 0.4 mm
